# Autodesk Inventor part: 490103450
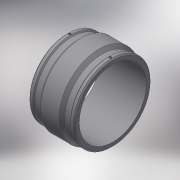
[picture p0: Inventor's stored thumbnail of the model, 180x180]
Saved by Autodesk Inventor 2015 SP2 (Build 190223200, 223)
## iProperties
Created: 2017-06
Part Number: 490103450
Material: Generic
Description: PLASSON COUPLER 450
Document SubType Name: Modeling
Designer: KIM
Mass: 16398.8 g
Surface Area: 10528.4 cm^2
Volume: 16398.8 cm^3
Density: 1 g/cm^3
Appearance: Default
Author: KIM
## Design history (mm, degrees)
derived "490103.ipt"
feature "Solid1::490103.ipt"
tag "TaggingFeature1"
body "Solid1"
other parameters: "d13" = 306, "d15" = 153, "d16" = 153, "d22" = 514, "d23" = 539, "d24" = 498.58, "d25" = 135 deg, "d26" = 122.4, "d27" = 135 deg, "d29" = 257, "d35" = 15, "d39" = 0, "d40" = 4, "d41" = 14, "d42" = 0, "d43" = 135 deg, "d44" = 33.66, "d46" = 6, "d47" = 0, "L_" = 306, "L_1" = 153, "D_" = 539, "A_" = 257, "d_2" = 12
